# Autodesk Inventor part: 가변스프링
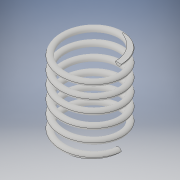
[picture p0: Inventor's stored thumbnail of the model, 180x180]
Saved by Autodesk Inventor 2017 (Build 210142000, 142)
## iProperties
Part Number: 가변스프링
Material: 일반
Document SubType Name: Modeling
Designer: 00-00
Density: 1 g/cm^3
Appearance: 기본값
Mass: 1.16503 g
Surface Area: 23.6146 cm^2
Volume: 1.16503 cm^3
Author: 00-00
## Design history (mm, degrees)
sketch "스케치1"
  geometry: L1 (0, 0)-(10, 0); L2 (10, 0)-(10, 26.7); L3 (10, 26.7)-(0, 26.7); L4 (0, 26.7)-(0, 0); C1 r 1 at (10, 0)
  constraints: 8 end point, 2 parallel, 1 centre point, 1 coincident, 1 horizontal, 1 perpendicular
  dimensions: "d0" = 20 diameter of L2 L4; "d1" = 2 diameter of C1; "d2" = 26.7 distance of L3.end L1.start (derived)
feature "코일1" sketch "스케치1" pitch "d3" = 26.7 (= d2); turns "d5" = 6; dims "d4" = 26.7 (= d2), "d6" = 0, angle "d7" = 90 deg, angle "d8" = 90 deg, "d9" = 0, "d10" = 0
node "작업 평면1"
sketch "스케치2"
  geometry: L1 (9, 0)-(11, 0) reference; 1 further point
  constraints: 1 horizontal alignment
extrude "돌출1" cut sketch "스케치2" stored distance "d12" = 10; taper "d13" = 0 deg
node "작업 평면3"
sketch "스케치3"
  geometry: L1 (-1, 0)-(1, 0) reference; 1 further point
  constraints: 1 horizontal alignment
extrude "돌출2" cut sketch "스케치3" stored distance "d15" = 10; taper "d16" = 0 deg
node "솔리드1"
node "절단 모서리 투영1"
node "절단 모서리 투영2"
other parameters: "d11" = 90 deg
